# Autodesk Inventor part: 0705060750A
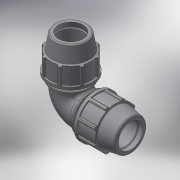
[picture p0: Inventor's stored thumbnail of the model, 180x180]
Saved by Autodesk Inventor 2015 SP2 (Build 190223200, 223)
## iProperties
Created: 2017-02
Part Number: 0705060750A
Material: Generic
Description: PLASSON 90° ELBOW 75-75
Document SubType Name: Modeling
Designer: KIM
Mass: 1923.39 g
Surface Area: 2516.77 cm^2
Volume: 1923.39 cm^3
Density: 1 g/cm^3
Appearance: Default
Author: KIM
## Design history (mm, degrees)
derived "87050.ipt"
feature "Solid1::87050.ipt"
tag "TaggingFeature1"
body "Solid1"
other parameters: "d2" = 75, "d4" = 14.83333, "d5" = 44.5, "d7" = 134, "d9" = 25.42857, "d11" = 5.93333, "d13" = 120 deg, "d14" = 97.5, "d15" = 10 deg, "d16" = 116.58, "d18" = 3.75, "d19" = 35 deg, "d20" = 17.5 deg, "d21" = 124.62, "d23" = 0, "d25" = 360 deg, "d27" = 2.68, "d33" = 1.5, "d42" = 60.52, "d43" = 4.02, "d46" = 2.25, "d51" = 178, "d59" = 90 deg, "d63" = 132, "d64" = 67.5, "d67" = 100.5, "d68" = 10.68, "d70" = 90 deg, "d71" = 11.25, "d72" = 8.93333, "d73" = 0, "d75" = 90 deg, "d77" = 114.2484, "d78" = 3.56, "d_" = 75, "E_" = 134, "A_" = 178, "l_" = 132
